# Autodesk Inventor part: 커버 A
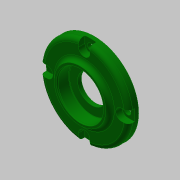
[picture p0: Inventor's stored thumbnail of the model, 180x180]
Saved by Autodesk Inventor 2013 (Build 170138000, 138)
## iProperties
Created: 2019-05
Part Number: 커버 A
Material: 알루미늄 6061
Document SubType Name: Modeling
Designer: mduedu
Density: 2.71 g/cm^3
Mass: 47.9629 g
Surface Area: 85.7291 cm^2
Volume: 17.6985 cm^3
Author: mduedu
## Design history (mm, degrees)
sketch "스케치1"
  geometry: C1 r 31 at (0, 0); 1 further point
  constraints: 1 centre point, 1 coincident
  dimensions: "d0" = 62 diameter of C1
extrude "돌출1" new body sketch "스케치1" distance "d1" = 7; taper "d2" = 0 deg
sketch "스케치2"
  geometry: C1 r 18 at (0, 0); 1 further point
  constraints: 1 centre point, 1 coincident
  dimensions: "d3" = 36 diameter of C1
extrude "돌출2" join sketch "스케치2" distance "d4" = 3; taper "d5" = 0 deg
fillet "모깎기1" dims "d6" = 3
sketch "스케치3"
  geometry: C1 r 20 at (0, 0); 1 further point
  constraints: 1 centre point, 1 coincident
  dimensions: "d7" = 40 diameter of C1
extrude "돌출3" join sketch "스케치3" distance "d8" = 4; taper "d9" = 0 deg
sketch "스케치4"
  geometry: C1 r 17 at (0, 0); 1 further point
  constraints: 1 centre point, 1 coincident
  dimensions: "d10" = 34 diameter of C1
extrude "돌출4" cut sketch "스케치4" distance "d11" = 3; taper "d12" = 0 deg
sketch "스케치5"
  geometry: C1 r 16 at (0, 0); 1 further point
  constraints: 1 centre point, 1 coincident
  dimensions: "d13" = 32 diameter of C1
extrude "돌출5" cut sketch "스케치5" distance "d14" = 8.3; taper "d15" = 0 deg
sketch "스케치6"
  geometry: C1 r 10 at (0, 0); 1 further point
  constraints: 1 centre point, 1 coincident
  dimensions: "d16" = 20 diameter of C1
extrude "돌출6" cut sketch "스케치6" stored distance "d17" = 8.3; taper "d18" = 0 deg
fillet "모깎기2" dims "d19" = 0.3
fillet "모깎기3" dims "d20" = 3
fillet "모깎기4" dims "d21" = 3
chamfer "모따기1" distance "d22" = 1; stored, may be unused: second distance "d23" = 2, angle "d24" = 45 deg
sketch "스케치7" dims "d25" = 52
  geometry: L1 (-4, 26)-(-4, 30.741); L2 (4, 26)-(4, 30.741); A1 r 4 centre (0, 26) between (-4, 26) and (4, 26); A2 r 31 centre (0, 0) between (4, 30.741) and (-4, 30.741); 3 further points
  constraints: 4 end point, 4 point on circle, 2 centre point, 2 coincident, 2 tangent, 2 vertical alignment, 1 parallel, 1 vertical, 4 other
  dimensions: "d26" = 8 distance between parallel lines of L2 L1
extrude "돌출7" cut sketch "스케치7" distance "d27" = 4.4; taper "d28" = 0 deg
chamfer "모따기2" distance "d32" = 0.8; stored, may be unused: second distance "d33" = 2, angle "d34" = 30 deg
sketch "스케치8" dims "d36" = 52
  geometry: 6 further points
  constraints: 2 vertical alignment, 1 coincident, 7 other
  dimensions: "d39" = 360 deg dimension on point (0, 0) point (0, 26) (derived)
sketch "스케치9"
  geometry: 4 further points
  constraints: 4 other
hole "구멍1" sketch "스케치9" at (-26, 0), (0, -26), (26, 0), (0, 26) diameter "d41" = 4.5; stored, may be unused: countersink angle "d45" = 90 deg, drill point angle "d47" = 0 deg; dims "d42" = 6, "d43" = 4, "d44" = 2, "d46" = 8
node "솔리드1"
pattern_circular "원형 패턴1" dims angle "d30" = 360 deg
